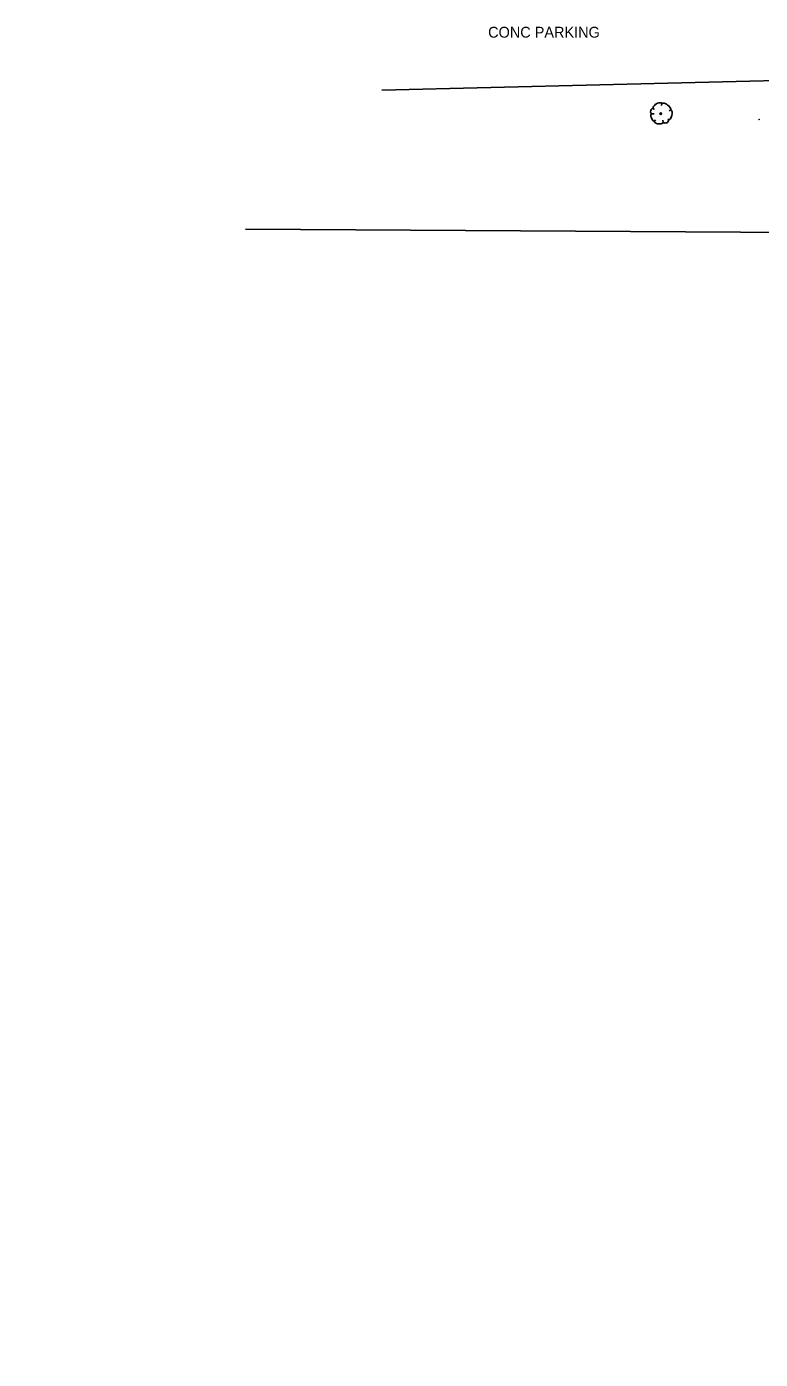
# Model space of a CAD drawing. Extents: x 1802180 to 1804859, y 572524 to 575172.
# Drawn here: x 1803144.4 to 1803314, y 574147.8 to 574455.6 of the extents above; entities that cross this region are included whole.
import ezdxf

# ---------------------------------------------------------------- set-up
doc = ezdxf.new("R2010")
doc.units = 0
for name, color, linetype in [('S_MISC_BOUNDARY', 7, 'Continuous'), ('S_PARKING', 7, 'Continuous'), ('S_PARKING_ANNOT', 7, 'Continuous'), ('S_TREE', 7, 'Continuous'), ('S_UTL_PT_SYM', 7, 'Continuous')]:
    doc.layers.add(name, color=color, linetype=linetype)

msp = doc.modelspace()

# ---------------------------------------------------------------- linework, layer by layer
at = {"layer": 'S_MISC_BOUNDARY'}
msp.add_lwpolyline([(1802879.24, 573886.73), (1803332.38, 573880.88), (1803406.04, 573888.6), (1803452.16, 573909.91), (1803480.86, 574044.75), (1803488.24, 574279.61), (1803486.64, 574405.44), (1803398.34, 574407.58), (1803194.96, 574408.85)], dxfattribs=at)
at = {"layer": 'S_PARKING'}
msp.add_lwpolyline([(1803226.44, 574440.89), (1803327.23, 574443.41), (1803334.54, 574446.41)], dxfattribs=at)
at = {"layer": 'S_TREE'}
for p, q in [((1803291.26, 574437.85), (1803291.05, 574437.38)), ((1803288.8, 574435.45), (1803289.42, 574435.45)), ((1803289.17, 574436.74), (1803289.45, 574436.42)), ((1803289.45, 574433.7), (1803289.7, 574434.09)), ((1803291.48, 574433.55), (1803291.43, 574433.98)), ((1803292.8, 574434.04), (1803292.54, 574434.28)), ((1803293.23, 574436.31), (1803292.87, 574436.16))]:
    msp.add_line(p, q, dxfattribs=at)
msp.add_circle((1803290.95, 574435.51), 0.188, dxfattribs=at)
for centre, major_axis, ratio, start_param, end_param in [((1803290.22, 574437.27), (1.02, 0.6), 0.471018, 0, 3.141593), ((1803292.23, 574437.09), (-1, 0.75), 0.405113, 3.141593, 6.283186), ((1803288.98, 574436.11), (0.168, 0.567), 0.646762, 0, 3.141593), ((1803289.15, 574434.64), (-0.337, 0.88), 0.420543, 6.283185, 9.424777), ((1803292.14, 574433.82), (0.602, 0.255), 0.711534, 3.141592, 6.283185), ((1803292.98, 574435.21), (0.25, 1.13), 0.482994, 3.141593, 6.283185), ((1803290.51, 574433.66), (-1.01, 0.11), 0.529943, 0, 3.141593)]:
    msp.add_ellipse(centre, major_axis=major_axis, ratio=ratio, start_param=start_param, end_param=end_param, dxfattribs=at)
at = {"layer": 'S_UTL_PT_SYM'}
msp.add_lwpolyline([(1803313.67, 574434.15), (1803313.67, 574434.2), (1803313.67, 574434.15), (1803313.62, 574434.15), (1803313.67, 574434.15), (1803313.67, 574434.1), (1803313.67, 574434.15), (1803313.72, 574434.15)], dxfattribs=at)

# ---------------------------------------------------------------- texts
at = {"layer": 'S_PARKING_ANNOT'}
msp.add_text('CONC PARKING', height=2.5, dxfattribs=at).set_placement((1803251.04, 574453.06))

doc.saveas('drawing.dxf')
